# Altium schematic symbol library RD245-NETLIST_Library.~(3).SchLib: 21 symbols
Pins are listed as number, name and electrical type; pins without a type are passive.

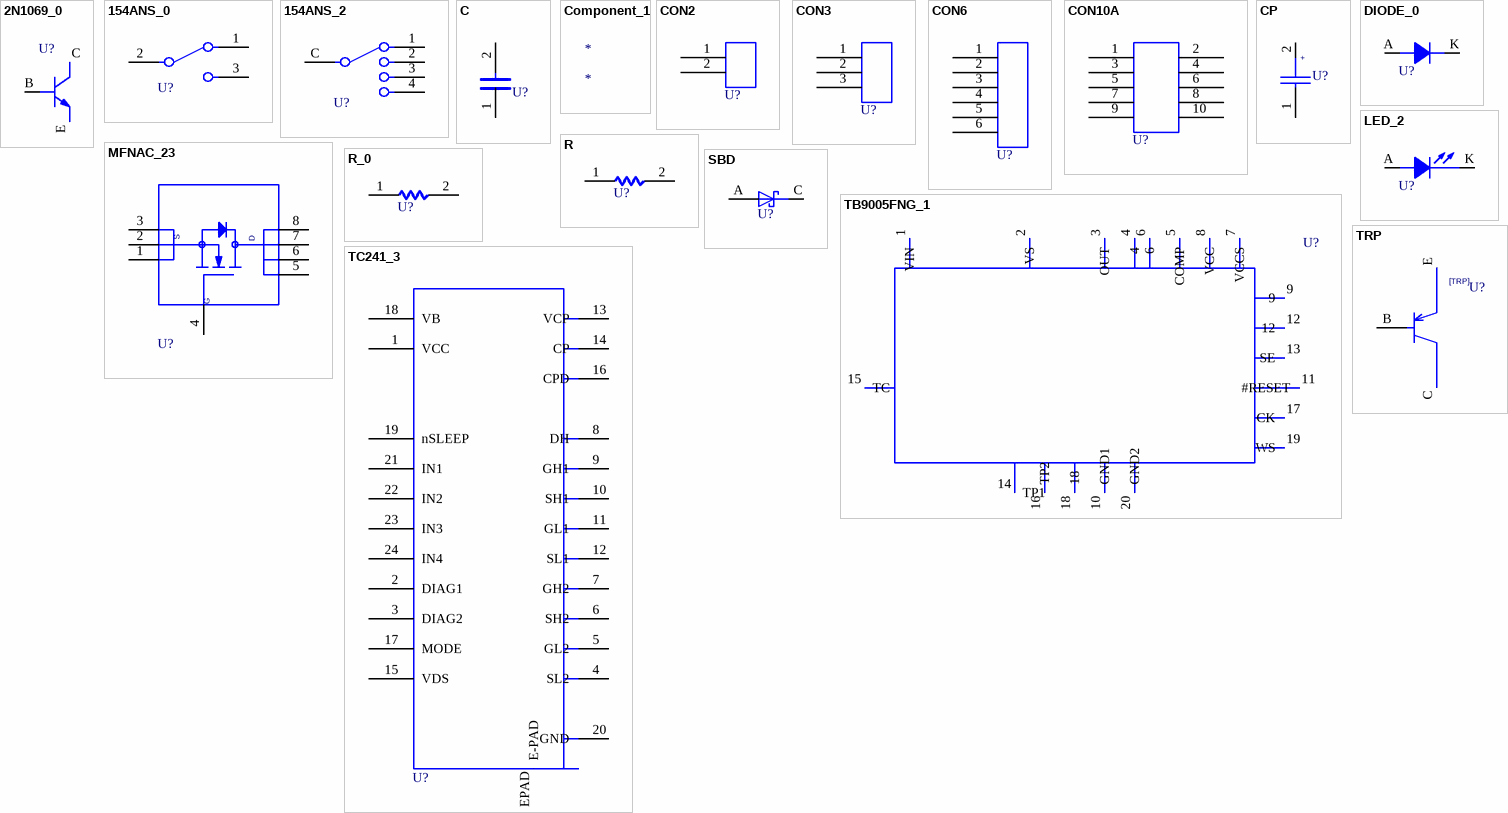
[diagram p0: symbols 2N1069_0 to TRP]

## 2N1069_0
designator U?  (value not drawn)
SAVECOUNT: 1; UPDATEUSER: sptcae13; UPDATETIME: 09:49:24; PSPICETEMPLATE: Q^@REFDES %C %B %E; OriginalSymbolOrigin: (0,5080); Altium-Right: 20; Altium-Bottom: 60
simulation model 2N1069_0
pins: B, C, E

## 154ANS_0
designator U?  (value not drawn)
SAVECOUNT: 1; UPDATEUSER: sptcae13; UPDATETIME: 09:49:24; OriginalSymbolOrigin: (-2540,0); Altium-Right: 40
pins: 1 NC, 2 COMMON, 3 NO

## 154ANS_2
designator U?  (value not drawn)
SAVECOUNT: 1; UPDATEUSER: sptcae13; UPDATETIME: 09:49:24; OriginalSymbolOrigin: (-2540,0); Altium-Right: 40; Altium-Bottom: 50
pins: 1 NC, 2 COMMON, 3 NO, 4 NO, C NO

## C
designator U?  (value not drawn)
UPDATETIME: 09:49:24; UPDATEUSER: sptcae13; SAVECOUNT: 1; ORIGINALSYMBOLORIGIN: (0,0); Altium-Right: 20; Altium-Bottom: 10
pins: 1, 2

## Component_1
designator *

## CON2
designator U?  (value not drawn)
SAVECOUNT: 1; UPDATEUSER: sptcae13; UPDATETIME: 09:49:24; OriginalSymbolOrigin: (0,0); Altium-Right: 20; Altium-Bottom: 30
pins: 1, 2

## CON3
designator U?  (value not drawn)
SAVECOUNT: 1; UPDATEUSER: sptcae13; UPDATETIME: 09:49:24; OriginalSymbolOrigin: (0,0); Altium-Right: 20; Altium-Bottom: 40
pins: 1, 2, 3

## CON6
designator U?  (value not drawn)
SAVECOUNT: 1; UPDATEUSER: sptcae13; UPDATETIME: 09:49:24; OriginalSymbolOrigin: (0,0); Altium-Right: 20; Altium-Bottom: 70
pins: 1, 2, 3, 4, 5, 6

## CON10A
designator U?  (value not drawn)
SAVECOUNT: 1; UPDATEUSER: sptcae13; UPDATETIME: 09:49:24; OriginalSymbolOrigin: (0,0); Altium-Right: 30; Altium-Bottom: 60
pins: 1, 2, 3, 4, 5, 6, 7, 8, 9, 10

## CP
designator U?  (value not drawn)
SAVEAREA0: -1450,-153,20294,13055; UPDATETIME: 09:49:24; UPDATEUSER: sptcae13; SAVECOUNT: 1; ORIGINALSYMBOLORIGIN: (0,0); Altium-Right: 20
pins: 1, 2

## DIODE_0
designator U?  (value not drawn)
SAVECOUNT: 1; UPDATEUSER: sptcae13; UPDATETIME: 09:49:24; OriginalSymbolOrigin: (0,0); Altium-Right: 30; Altium-Bottom: 20
pins: A, K

## LED_2
designator U?  (value not drawn)
SAVECOUNT: 1; UPDATEUSER: sptcae13; UPDATETIME: 09:49:24; OriginalSymbolOrigin: (0,0); Altium-Right: 40; Altium-Bottom: 20
pins: A, K

## MFNAC_23
designator U?, comment MFNAC  (value not drawn)
SAVEAREA0: -10143,-336,37609,28718; UPDATETIME: 09:49:24; UPDATEUSER: sptcae13; COMP: MFNAC_23; SAVECOUNT: 1; ORIGINALSYMBOLORIGIN: (0,0); Altium-Right: 80
pins: 1, 2, 3, 4, 5, 6, 7, 8

## R
designator U?  (value not drawn)
UPDATETIME: 09:49:24; UPDATEUSER: sptcae13; SAVECOUNT: 1; ORIGINALSYMBOLORIGIN: (0,0); Altium-Right: 20
pins: 1, 2

## R_0
designator U?, comment R  (value not drawn)
SAVECOUNT: 1; COMP: R_0; UPDATEUSER: sptcae13; UPDATETIME: 09:49:24; ORIGINALSYMBOLORIGIN: (0,0); Altium-Right: 20
pins: 1, 2

## SBD
designator U?  (value not drawn)
SAVEAREA0: -4630,-153,17114,13055; UPDATETIME: 09:49:24; UPDATEUSER: sptcae13; SAVECOUNT: 1; ORIGINALSYMBOLORIGIN: (0,0); Altium-Right: 20
pins: A, C

## TB9005FNG_1
designator U?, comment TB9005FNG  (value not drawn)
SAVEAREA0: -26622,-27385,86055,19754; UPDATETIME: 09:49:24; UPDATEUSER: sptcae13; COMP: TB9005FNG_1; SAVECOUNT: 1; ORIGINALSYMBOLORIGIN: (-5080,5080); Altium-Right: 290; Altium-Bottom: 170
pins: 1 VIN (in), 2 VS (in), 3 OUT (out), 4, 5 COMP (in), 6, 7 VCCS (in), 8 VCC (in), 9, 10 GND1 (in), 11 #RESET (out), 12, 13 SE (in), 14 TP1 (in), 15 TC, 16 TP2 (in), 17 CK (in), 18, 19 WS (in), 20 GND2 (in)

## TC241_3
designator U?  (value not drawn)
SAVECOUNT: 1; UPDATEUSER: sptcae13; UPDATETIME: 09:49:24; OriginalSymbolOrigin: (0,0); Altium-Right: 110; Altium-Bottom: 320
pins: 1 VCC, 2 DIAG1, 3 DIAG2, 4 SL2, 5 GL2, 6 SH2, 7 GH2, 8 DH, 9 GH1, 10 SH1, 11 GL1, 12 SL1, 13 VCP, 14 CP, 15 VDS, 16 CPD, 17 MODE, 18 VB, 19 nSLEEP, 20 GND, 21 IN1, 22 IN2, 23 IN3, 24 IN4, EPAD E-PAD

## TRP
designator U?  (value not drawn)
SAVEAREA0: -5466,-244,29263,20886; UPDATETIME: 09:49:23; UPDATEUSER: sptcae13; SAVECOUNT: 1; ORIGINALSYMBOLORIGIN: (0,0); Altium-Right: 20; Altium-Bottom: 100
pins: B, C, E

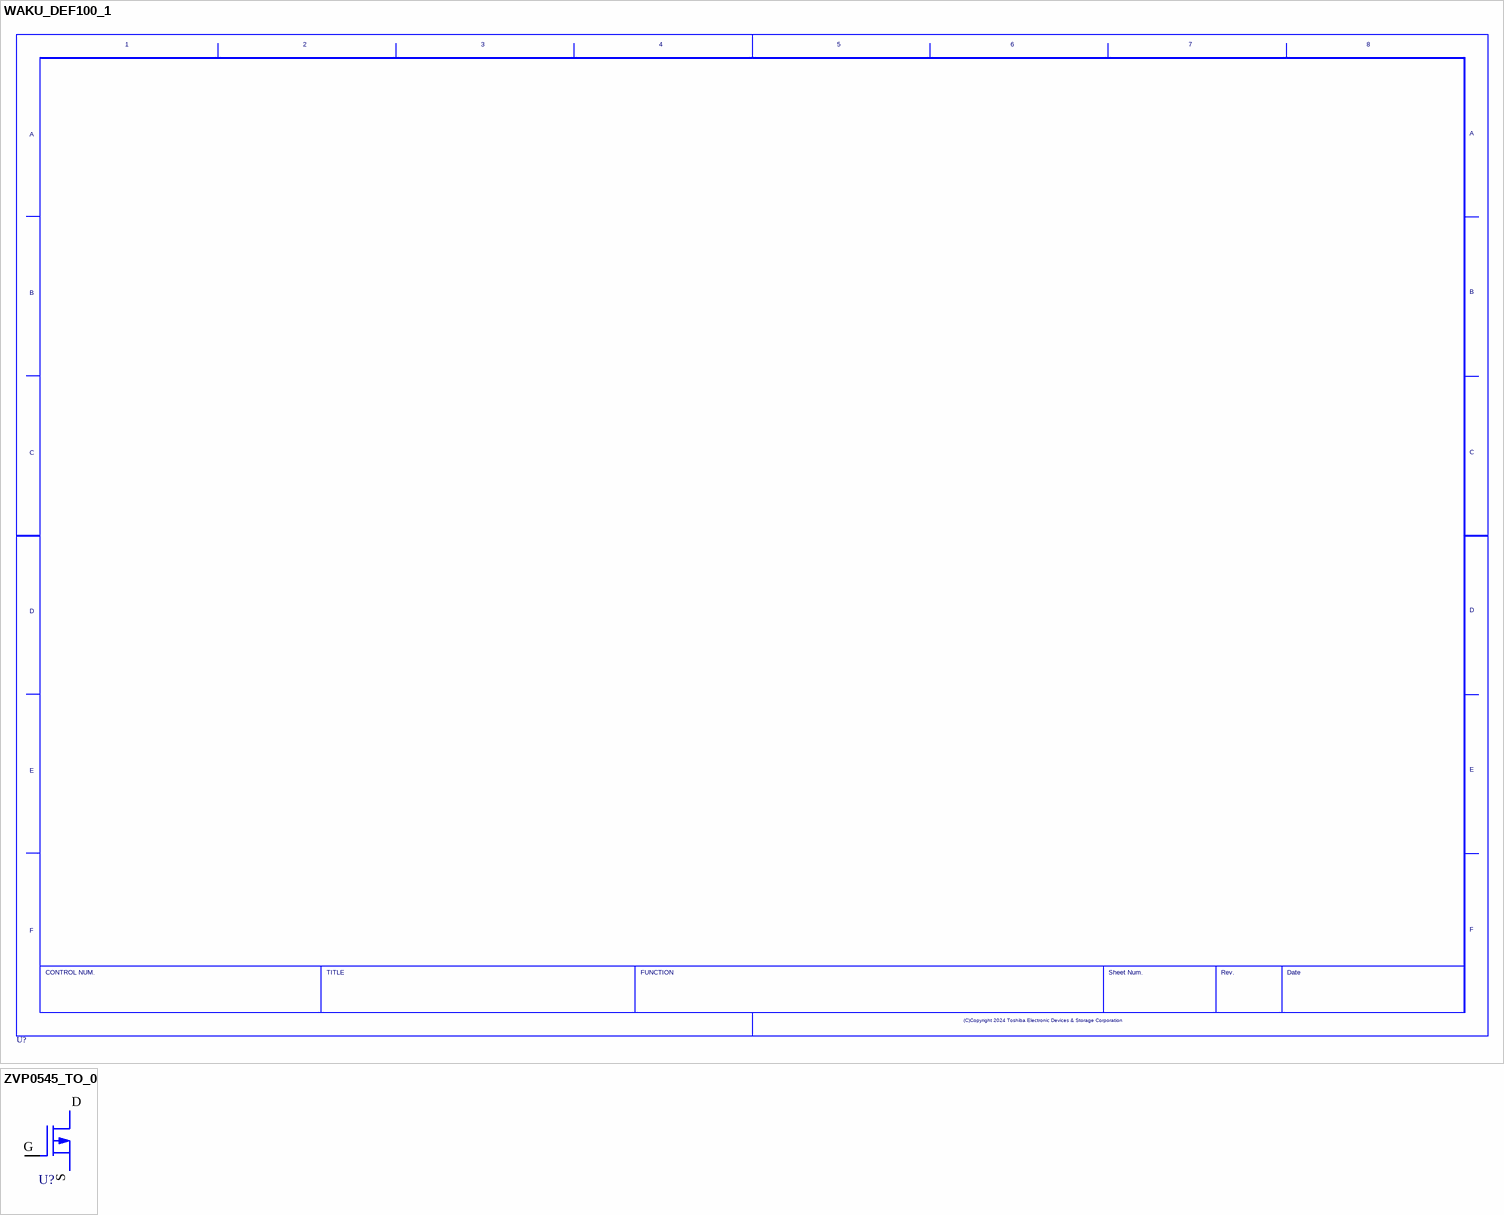
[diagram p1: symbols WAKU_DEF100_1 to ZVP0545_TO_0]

## WAKU_DEF100_1
designator U?, comment WAKU_DEF100  (value not drawn)
SAVECOUNT: 1; UPDATEUSER: sptcae13; UPDATETIME: 09:49:24; PLOTTIME: HH:MM; SAVEAREA0: -63393,-16950,474261,314592; ORIGINALSYMBOLORIGIN: (0,0); Altium-Right: 1570; Altium-Bottom: 1070

## ZVP0545_TO_0
designator U?  (value not drawn)
SAVECOUNT: 1; UPDATEUSER: sptcae13; UPDATETIME: 09:49:23; OriginalSymbolOrigin: (0,5080); Altium-Right: 20; Altium-Bottom: 60
pins: D, G, S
